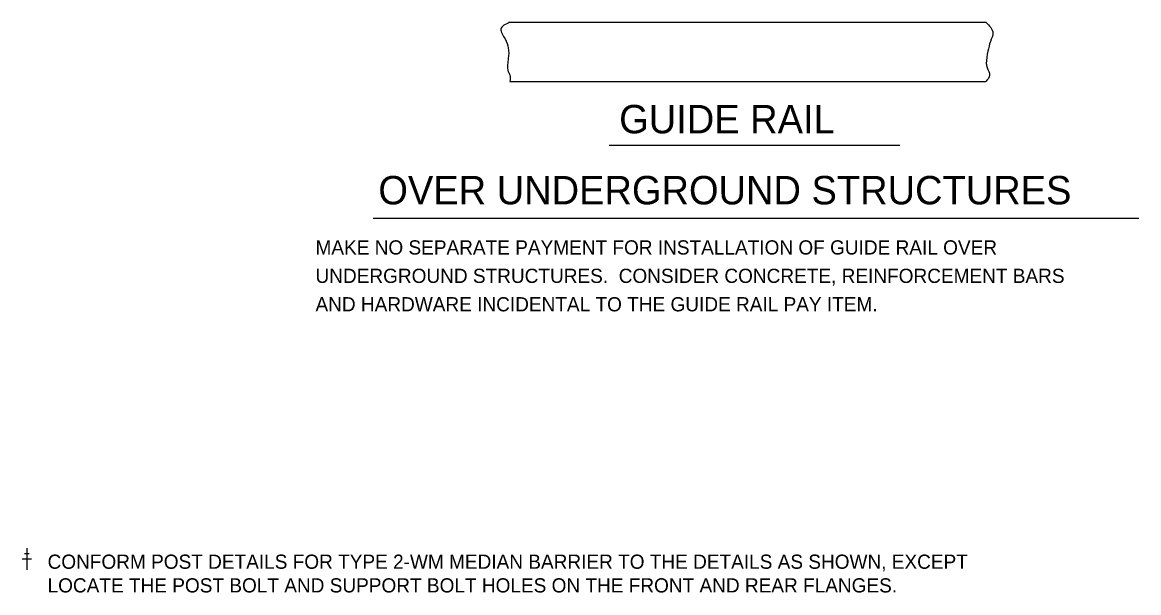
# Model space of a CAD drawing. Extents: x 637628 to 640188, y 298266 to 300751.
# Drawn here: x 637984.3 to 638219.8, y 298823 to 298943.4 of the extents above; entities that cross this region are included whole.
import ezdxf

# ---------------------------------------------------------------- set-up
doc = ezdxf.new("R2010")
doc.units = 0
doc.layers.add('2', color=7, linetype='Continuous')
doc.layers.add('3', color=7, linetype='Continuous')

msp = doc.modelspace()

# ---------------------------------------------------------------- linework, layer by layer
at = {"layer": '2'}
for p, q in [((638087.12, 298943.41), (638187.55, 298943.41)), ((638087.12, 298930.91), (638187.55, 298930.91))]:
    msp.add_line(p, q, dxfattribs=at)
for points in [[(638087.12, 298943.41), (638085.24, 298941.99), (638086.12, 298939.9), (638086.81, 298938), (638086.81, 298935.74), (638086.64, 298934.51), (638086.81, 298932.96), (638087.16, 298932.27), (638087.12, 298930.91)], [(638187.55, 298943.41), (638189.04, 298941.12), (638188.52, 298939.38), (638187.99, 298937.3), (638187.65, 298934.69), (638187.82, 298933.84), (638188.34, 298932.27), (638187.55, 298930.91)]]:
    msp.add_spline(points, degree=3, dxfattribs=at)
at = {"layer": '3'}
for p, q in [((638108.06, 298917.5), (638169.39, 298917.5)), ((638058.29, 298902.08), (638219.79, 298902.08)), ((637984.74, 298831.23), (637985.24, 298831.23)), ((637985.24, 298832.38), (637985.24, 298827.8)), ((637985.24, 298832.38), (637985.24, 298830.09)), ((637985.24, 298831.23), (637985.74, 298831.23)), ((637984.28, 298830.09), (637985.24, 298830.09)), ((637985.24, 298830.09), (637986.19, 298830.09))]:
    msp.add_line(p, q, dxfattribs=at)

# ---------------------------------------------------------------- texts
for s, height, p in [('GUIDE RAIL', 6, (638110.19, 298919.97)), ('OVER UNDERGROUND STRUCTURES', 6, (638059.39, 298904.97)), ('MAKE NO SEPARATE PAYMENT FOR INSTALLATION OF GUIDE RAIL OVER', 3, (638046.13, 298894.38)), ('UNDERGROUND STRUCTURES.  CONSIDER CONCRETE, REINFORCEMENT BARS', 3, (638046.13, 298888.38)), ('AND HARDWARE INCIDENTAL TO THE GUIDE RAIL PAY ITEM.', 3, (638046.13, 298882.38)), ('CONFORM POST DETAILS FOR TYPE 2-WM MEDIAN BARRIER TO THE DETAILS AS SHOWN, EXCEPT ', 3, (637989.61, 298828.02)), ('LOCATE THE POST BOLT AND SUPPORT BOLT HOLES ON THE FRONT AND REAR FLANGES.', 3, (637989.61, 298823.02))]:
    msp.add_text(s, height=height, dxfattribs=at).set_placement(p)

doc.saveas('drawing.dxf')
